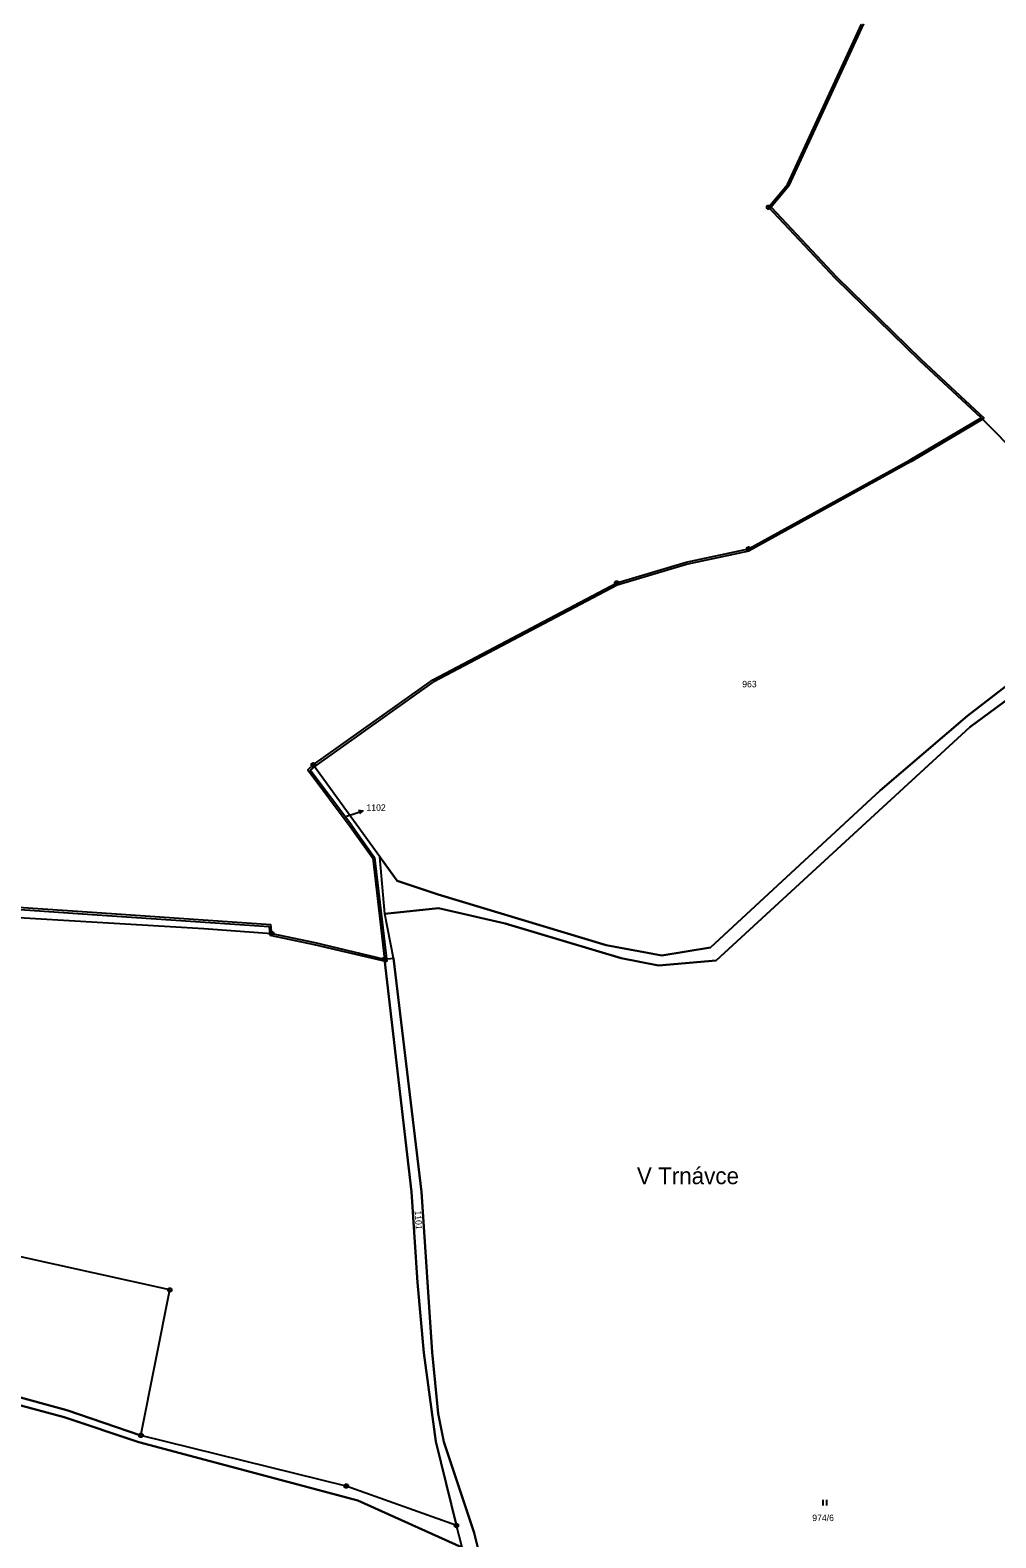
# Model space of a CAD drawing. Extents: x -654083 to -650132, y -1099819 to -1096699.
# Drawn here: x -653426.1 to -653172.4, y -1097445.7 to -1097049.6 of the extents above; entities that cross this region are included whole.
import ezdxf

# ---------------------------------------------------------------- set-up
doc = ezdxf.new("R2010")
doc.units = 0
for name, color, linetype in [('Geodetické body', 7, 'Continuous'), ('Názvy', 7, 'Continuous'), ('Obvody jako plochy', 7, 'Continuous'), ('Ostatní hranice', 7, 'Continuous'), ('Parcelní čísla', 7, 'Continuous'), ('Prvky pro prodl_ par_ č_', 7, 'Continuous'), ('Značky kultur', 7, 'Continuous')]:
    doc.layers.add(name, color=color, linetype=linetype)

msp = doc.modelspace()

# ---------------------------------------------------------------- linework, layer by layer
at = {"layer": 'Geodetické body'}
for centre, radius in [((-653232.1, -1097096.14), 0.5), ((-653232.1, -1097096.14), 0.001), ((-653237.34, -1097185.9), 0.5), ((-653237.34, -1097185.9), 0.001), ((-653272.01, -1097194.84), 0.5), ((-653272.01, -1097194.84), 0.001), ((-653351.71, -1097242.64), 0.5), ((-653351.71, -1097242.64), 0.001), ((-653362.65, -1097286.95), 0.5), ((-653362.65, -1097286.95), 0.001), ((-653333.01, -1097293.67), 0.5), ((-653333.01, -1097293.67), 0.001), ((-653389.4, -1097380.59), 0.5), ((-653389.4, -1097380.59), 0.001), ((-653397, -1097418.8), 0.5), ((-653397, -1097418.8), 0.001), ((-653343.04, -1097432.11), 0.5), ((-653343.04, -1097432.11), 0.001), ((-653314.13, -1097442.47), 0.5), ((-653314.13, -1097442.47), 0.001)]:
    msp.add_circle(centre, radius, dxfattribs=at)
at = {"layer": 'Obvody jako plochy'}
for points in [[(-653169.37, -1097021.12), (-653123.6, -1097064.72), (-653099.3, -1097092.93), (-653077.63, -1097115.6), (-653052.6, -1097138.9), (-653022.01, -1097167.89), (-652983.92, -1097203.79), (-652960.77, -1097256.52), (-652971.41, -1097253.48), (-652995.31, -1097253.12), (-653025.72, -1097250.99), (-653058.47, -1097240.4), (-653110.76, -1097212.87), (-653144.53, -1097183.42), (-653176.26, -1097151.49), (-653192.37, -1097136.45), (-653214.5, -1097114.82), (-653232.1, -1097096.14), (-653227.13, -1097090.2), (-653207.69, -1097048.07)], [(-653167.23, -1097223.86), (-653179.19, -1097232.71), (-653197.67, -1097249.71), (-653245.87, -1097294.01), (-653261.05, -1097295.33), (-653270.85, -1097293.42), (-653301.33, -1097284.36), (-653318.82, -1097280.25), (-653332.89, -1097281.75), (-653334.22, -1097266.8), (-653329.65, -1097273.1), (-653318.91, -1097276.71), (-653274.73, -1097289.98), (-653260.15, -1097292.75), (-653247.34, -1097290.66), (-653202.82, -1097249.36), (-653179.86, -1097229.74), (-653158.36, -1097213.2)], [(-653305.27, -1097461.55), (-653309.45, -1097444.38), (-653317.43, -1097420.53), (-653318.91, -1097413.09), (-653320.48, -1097396.97), (-653323.29, -1097354.78), (-653330.64, -1097293.46), (-653332.89, -1097281.75), (-653318.82, -1097280.25), (-653301.33, -1097284.36), (-653270.85, -1097293.42), (-653261.05, -1097295.33), (-653245.87, -1097294.01), (-653197.67, -1097249.71), (-653179.19, -1097232.71), (-653167.23, -1097223.86)], [(-653433.54, -1097282.51), (-653380.47, -1097285.64), (-653362.65, -1097286.95), (-653351.35, -1097289.33), (-653333.01, -1097293.67), (-653325.89, -1097354.85), (-653324.32, -1097378.65), (-653322.66, -1097397.15), (-653319.55, -1097420.4), (-653314.13, -1097442.47), (-653343.04, -1097432.11), (-653397, -1097418.8), (-653389.4, -1097380.59), (-653458.8, -1097365.2)], [(-653433.54, -1097282.51), (-653380.47, -1097285.64), (-653362.65, -1097286.95), (-653362.88, -1097284.64), (-653409.79, -1097281.47), (-653435.79, -1097279.66)]]:
    msp.add_lwpolyline(points, dxfattribs=at)
for points in [[(-653176.26, -1097151.49), (-653144.53, -1097183.42), (-653110.76, -1097212.87), (-653123.81, -1097210.51), (-653144.74, -1097208.65), (-653158.36, -1097213.2), (-653179.86, -1097229.74), (-653202.82, -1097249.36), (-653247.34, -1097290.66), (-653260.15, -1097292.75), (-653274.73, -1097289.98), (-653318.91, -1097276.71), (-653329.65, -1097273.1), (-653334.22, -1097266.8), (-653351.71, -1097242.64), (-653320.34, -1097220.31), (-653272.01, -1097194.84), (-653253.76, -1097189.4), (-653237.34, -1097185.9), (-653194.87, -1097162.47)], [(-653332.89, -1097281.75), (-653334.22, -1097266.8), (-653351.71, -1097242.64), (-653353.19, -1097243.91), (-653342.02, -1097258.83), (-653336.1, -1097267.15), (-653333.01, -1097293.67), (-653330.64, -1097293.46)], [(-653309.45, -1097444.38), (-653305.27, -1097461.55), (-653307.98, -1097462.85), (-653316.08, -1097473.12), (-653328.07, -1097500.74), (-653333.73, -1097499.1), (-653321.24, -1097473.8), (-653310.75, -1097456.23), (-653312.64, -1097448.26), (-653314.13, -1097442.47), (-653319.55, -1097420.4), (-653322.66, -1097397.15), (-653324.32, -1097378.65), (-653325.89, -1097354.85), (-653333.01, -1097293.67), (-653330.64, -1097293.46), (-653323.29, -1097354.78), (-653320.48, -1097396.97), (-653318.91, -1097413.09), (-653317.43, -1097420.53)], [(-653458.8, -1097365.2), (-653459.71, -1097366.56), (-653523.63, -1097355.65), (-653581.76, -1097342.43), (-653653.22, -1097320.21), (-653671.12, -1097370.57), (-653620.34, -1097374.05), (-653579.33, -1097373.35), (-653463.66, -1097399.35), (-653416.5, -1097412.22), (-653397, -1097418.8), (-653389.4, -1097380.59)], [(-653417.21, -1097414.05), (-653397.59, -1097420.6), (-653339.99, -1097435.94), (-653312.64, -1097448.26), (-653314.13, -1097442.47), (-653343.04, -1097432.11), (-653397, -1097418.8), (-653416.5, -1097412.22), (-653463.66, -1097399.35), (-653579.33, -1097373.35), (-653620.34, -1097374.05), (-653671.12, -1097370.57), (-653672.13, -1097372.92), (-653621.26, -1097376.04), (-653579.29, -1097376.29), (-653463.76, -1097401.53)], [(-653633.51, -1097416.34), (-653512.94, -1097447.98), (-653333.73, -1097499.1), (-653321.24, -1097473.8), (-653310.75, -1097456.23), (-653312.64, -1097448.26), (-653339.99, -1097435.94), (-653397.59, -1097420.6), (-653417.21, -1097414.05), (-653463.76, -1097401.53), (-653579.29, -1097376.29), (-653621.26, -1097376.04)]]:
    msp.add_lwpolyline(points, close=True, dxfattribs=at)
at = {"layer": 'Ostatní hranice'}
for p, q in [((-653226.68, -1097090.42), (-653207.07, -1097047.92)), ((-653226.68, -1097090.42), (-653231.43, -1097096.12)), ((-653231.43, -1097096.12), (-653214.15, -1097114.47)), ((-653214.15, -1097114.47), (-653192, -1097136.11)), ((-653192, -1097136.11), (-653175.42, -1097151.58)), ((-653194.63, -1097162.91), (-653175.42, -1097151.58)), ((-653194.63, -1097162.91), (-653237.22, -1097186.4)), ((-653253.66, -1097189.89), (-653237.22, -1097186.4)), ((-653271.84, -1097195.32), (-653253.66, -1097189.89)), ((-653320.04, -1097220.72), (-653271.84, -1097195.32)), ((-653320.04, -1097220.72), (-653351.4, -1097243.04)), ((-653351.4, -1097243.04), (-653352.51, -1097244)), ((-653341.6, -1097258.56), (-653352.51, -1097244)), ((-653341.6, -1097258.56), (-653335.64, -1097266.95)), ((-653335.64, -1097266.95), (-653332.43, -1097294.32)), ((-653435.83, -1097280.16), (-653409.83, -1097281.97)), ((-653409.83, -1097281.97), (-653363.35, -1097285.12)), ((-653363.35, -1097285.12), (-653363.12, -1097287.35)), ((-653363.12, -1097287.35), (-653351.47, -1097289.82)), ((-653351.47, -1097289.82), (-653332.43, -1097294.32))]:
    msp.add_line(p, q, dxfattribs=at)
at = {"layer": 'Prvky pro prodl_ par_ č_'}
for p, q in [((-653343.02, -1097256.11), (-653341.6, -1097255.65)), ((-653341.6, -1097255.65), (-653338.74, -1097254.73))]:
    msp.add_line(p, q, dxfattribs=at)
msp.add_lwpolyline([(-653339.85, -1097254.56), (-653338.74, -1097254.73), (-653339.54, -1097255.51)], dxfattribs=at)
at = {"layer": 'Značky kultur'}
for p, q in [((-653217.85, -1097435.77), (-653217.85, -1097437.27)), ((-653216.83, -1097437.27), (-653216.83, -1097435.77))]:
    msp.add_line(p, q, dxfattribs=at)

# ---------------------------------------------------------------- texts
at = {"layer": 'Názvy'}
msp.add_text('V Trnávce', height=4.4, dxfattribs=at).set_placement((-653266.69, -1097352.81))
at = {"layer": 'Parcelní čísla'}
for s, height, p in [('963', 1.7, (-653239.03, -1097222.27)), ('1102', 0.1, (-653343.13, -1097256.11)), ('974/6', 1.7, (-653220.63, -1097441.33))]:
    msp.add_text(s, height=height, dxfattribs=at).set_placement(p)
msp.add_text('1101', height=1.7, rotation=273.276, dxfattribs=at).set_placement((-653325.09, -1097359.76))
at = {"layer": 'Prvky pro prodl_ par_ č_'}
msp.add_text('1102', height=1.7, dxfattribs=at).set_placement((-653337.74, -1097254.73))

doc.saveas('drawing.dxf')
